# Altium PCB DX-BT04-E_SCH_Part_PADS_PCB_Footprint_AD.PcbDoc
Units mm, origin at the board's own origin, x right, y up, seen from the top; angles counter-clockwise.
Board outline 152.4 x 101.6 mm, 2 copper layers (Top, Bottom), stack 0.323 mm thick; 1 components, 0 nets, 22 pads, 0 vias.
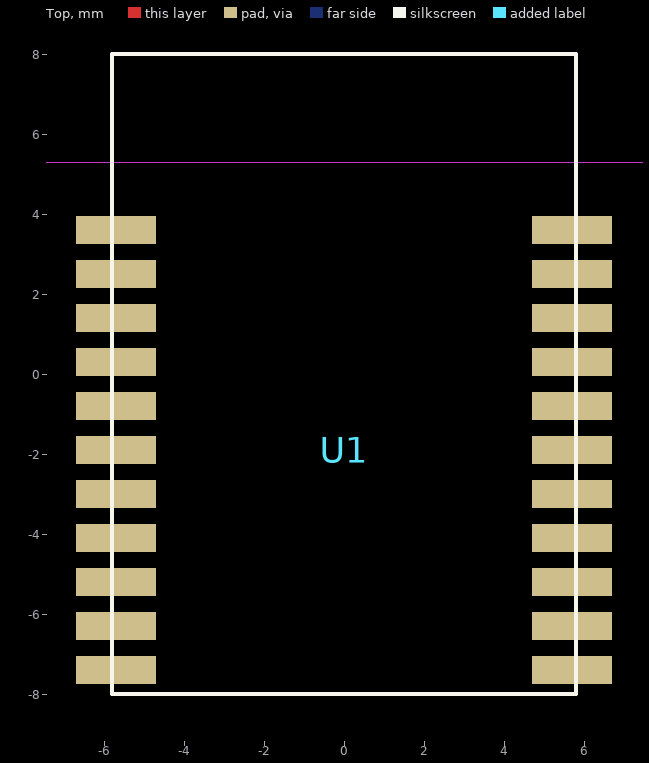
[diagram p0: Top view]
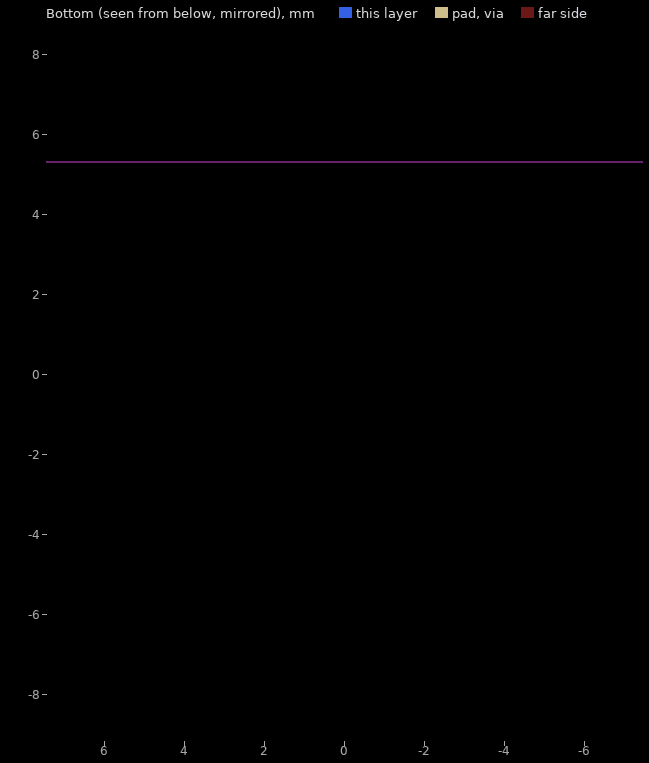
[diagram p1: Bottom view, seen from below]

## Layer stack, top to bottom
Solder Mask Top: solder mask 0.0102, Solder Resist, Dk 3.5
Top: signal copper 0.0343
Dielectric 1: dielectric 0.254, FR-4, Dk 4.3
Bottom: signal copper 0.0343
Solder Mask Bottom: solder mask 0.0102, Solder Resist, Dk 3.5

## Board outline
-694.363,-676.631 -541.963,-676.631 -541.963,-575.031 -694.363,-575.031

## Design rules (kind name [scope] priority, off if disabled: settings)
Clearance "'Default' PADS rule_17" [All] p1: gap=0.152 ignorepadtopadclearanceinfootprint=FALSE except(0: Arc-Hole Track-Hole SMDPad-Hole THPad-Hole Via-Hole Fill-Hole Poly-Hole Region-Hole Text-Hole)
Clearance "'Default' PADS rule_16" [InPolygon vs InPolygon] p2: gap=0.2 ignorepadtopadclearanceinfootprint=FALSE except(0: Arc-Hole Track-Hole SMDPad-Hole THPad-Hole Via-Hole Fill-Hole Poly-Hole Region-Hole Text-Hole)
Clearance "'Default' PADS rule_15" [All] p3: gap=0.152 ignorepadtopadclearanceinfootprint=FALSE except(0: Arc-Hole Track-Hole SMDPad-Hole THPad-Hole Via-Hole Fill-Hole Poly-Hole Region-Hole Text-Hole)
ComponentClearance "'Default' PADS rule_12" [All] p1: gap=0 collisioncheckmode=3 verticalgap=0.254 showdistances=FALSE
FlightTimeFalling "'Default' PADS rule_10" [All] p1: maximum=10.00
FlightTimeRising "'Default' PADS rule_9" [All] p1: maximum=10.00
Length "'Default' PADS rule_5" [All] p1: maxlimit=1270 minlimit=0
MatchedLengths "'Default' PADS rule_11" [InNetClass('All Nets')] p1: tolerance=5.08 checknetsindiffpair=TRUE checkdiffpairvsdiffpair=FALSE checkxsignals=FALSE checkothers=FALSE
MaxMinImpedance "'Default' PADS rule_8" [All] p1: minimum=50.00 maximum=150.0
ParallelSegment "'Default' PADS rule_7" [All] p1: limit=25.4 gap=5.08
ParallelSegment "'Default' PADS rule_6" [All] p2: limit=25.4 gap=5.08
PlaneClearance "'Default' PADS rule_14" [All] p1: clearance=0.2
PlaneConnect "Power Plane Connect Style - Via from round thru-hole global defaults" [IsVia] p1: planeconnectstyle=Direct reliefexpansion=0.508 reliefentries=4 reliefconductorwidth=0.381 reliefairgap=0.254
PlaneConnect "Power Plane Connect Style - Round thru-hole pad from global defaults" [IsPad And OnMultiLayer And (PadShape_MidLayer1 = 'Round') And (PadXSize_MidLayer1 = PadYSize_MidLayer1)] p2: planeconnectstyle=Direct reliefexpansion=0.508 reliefentries=4 reliefconductorwidth=0.381 reliefairgap=0.254
PlaneConnect "Power Plane Connect Style - Square thru-hole pad from global defaults" [IsPad And OnMultiLayer And ((PadShape_MidLayer1 = 'Rectangular') Or (PadShape_MidLayer1 = 'Octagonal') Or (PadShape_MidLayer1 = 'Rounded Rectangle')) And (PadXSize_MidLayer1 = PadYSize_MidLayer1)] p3: planeconnectstyle=Direct reliefexpansion=0.508 reliefentries=4 reliefconductorwidth=0.381 reliefairgap=0.254
PlaneConnect "Power Plane Connect Style - Rect thru-hole pad from global defaults" [IsPad And OnMultiLayer And ((PadShape_MidLayer1 = 'Rectangular') Or (PadShape_MidLayer1 = 'Octagonal') Or (PadShape_MidLayer1 = 'Rounded Rectangle')) And (PadXSize_MidLayer1 <> PadYSize_MidLayer1)] p4: planeconnectstyle=Direct reliefexpansion=0.508 reliefentries=4 reliefconductorwidth=0.381 reliefairgap=0.254
PlaneConnect "Power Plane Connect Style - Square-rect thru-hole pad from global defaults" [IsPad And OnMultiLayer And (PadShape_MidLayer1 = 'Rounded Rectangle') And (PadXSize_MidLayer1 = PadYSize_MidLayer1) And (Pad_CornerRadius_MidLayer1 = '0%')] p5: planeconnectstyle=Direct reliefexpansion=0.508 reliefentries=4 reliefconductorwidth=0.381 reliefairgap=0.254
PlaneConnect "Power Plane Connect Style - Oval thru-hole pad from global defaults" [IsPad And OnMultiLayer And (PadShape_MidLayer1 = 'Round') And (PadXSize_MidLayer1 <> PadYSize_MidLayer1)] p6: planeconnectstyle=Direct reliefexpansion=0.508 reliefentries=4 reliefconductorwidth=0.381 reliefairgap=0.254
PlaneConnect "Power Plane Connect Style - Round-oval thru-hole pad from global defaults" [IsPad And OnMultiLayer And (PadShape_MidLayer1 = 'Rounded Rectangle') And (PadXSize_MidLayer1 = PadYSize_MidLayer1) And (Pad_CornerRadius_MidLayer1 = '100%')] p7: planeconnectstyle=Direct reliefexpansion=0.508 reliefentries=4 reliefconductorwidth=0.381 reliefairgap=0.254
PolygonConnect "Polygon Connect Style - Bottom Round SMD from global defaults" [IsSMTPin And (PadShape_BottomLayer = 'Round') And (PadXSize_BottomLayer = PADYSize_BottomLayer) vs Layer = 'Bottom'] p1: connectstyle=Direct reliefconductorwidth=0.254 reliefentries=4 polygonreliefangle="45 Angle" airgapwidth=0.254
PolygonConnect "Polygon Connect Style - Top Round SMD from global defaults" [IsSMTPin And (PadShape_TopLayer = 'Round') And (PadXSize_TopLayer = PADYSize_TopLayer) vs Layer = 'Top'] p2: connectstyle=Direct reliefconductorwidth=0.254 reliefentries=4 polygonreliefangle="45 Angle" airgapwidth=0.254
PolygonConnect "Polygon Connect Style - Bottom Square SMD from global defaults 1" [IsSMTPin And (PadShape_BottomLayer = 'Rectangular') And (PadXSize_BottomLayer = PADYSize_BottomLayer) vs Layer = 'Bottom'] p3: connectstyle=Direct reliefconductorwidth=0.254 reliefentries=4 polygonreliefangle="45 Angle" airgapwidth=0.254
PolygonConnect "Polygon Connect Style - Bottom Square SMD from global defaults 2" [IsSMTPin And (PadShape_BottomLayer = 'Octagonal') And (PadXSize_BottomLayer = PADYSize_BottomLayer) vs Layer = 'Bottom'] p4: connectstyle=Direct reliefconductorwidth=0.254 reliefentries=4 polygonreliefangle="45 Angle" airgapwidth=0.254
PolygonConnect "Polygon Connect Style - Bottom Square SMD from global defaults 3" [IsSMTPin And (PadShape_BottomLayer = 'Rounded Rectangle') And (PadXSize_BottomLayer = PADYSize_BottomLayer) vs Layer = 'Bottom'] p5: connectstyle=Direct reliefconductorwidth=0.254 reliefentries=4 polygonreliefangle="45 Angle" airgapwidth=0.254
PolygonConnect "Polygon Connect Style - Top Square SMD from global defaults 1" [IsSMTPin And (PadShape_TopLayer = 'Rectangular') And (PadXSize_TopLayer = PADYSize_TopLayer) vs Layer = 'Top'] p6: connectstyle=Direct reliefconductorwidth=0.254 reliefentries=4 polygonreliefangle="45 Angle" airgapwidth=0.254
PolygonConnect "Polygon Connect Style - Top Square SMD from global defaults 2" [IsSMTPin And (PadShape_TopLayer = 'Octagonal') And (PadXSize_TopLayer = PADYSize_TopLayer) vs Layer = 'Top'] p7: connectstyle=Direct reliefconductorwidth=0.254 reliefentries=4 polygonreliefangle="45 Angle" airgapwidth=0.254
PolygonConnect "Polygon Connect Style - Top Square SMD from global defaults 3" [IsSMTPin And (PadShape_TopLayer = 'Rounded Rectangle') And (PadXSize_TopLayer = PADYSize_TopLayer) vs Layer = 'Top'] p8: connectstyle=Direct reliefconductorwidth=0.254 reliefentries=4 polygonreliefangle="45 Angle" airgapwidth=0.254
PolygonConnect "Polygon Connect Style - Bottom Rect SMD from global defaults 1" [IsSMTPin And (PadShape_BottomLayer = 'Rectangular') And (PadXSize_BottomLayer <> PADYSize_BottomLayer) vs Layer = 'Bottom'] p9: connectstyle=Direct reliefconductorwidth=0.254 reliefentries=4 polygonreliefangle="45 Angle" airgapwidth=0.254
PolygonConnect "Polygon Connect Style - Bottom Rect SMD from global defaults 2" [IsSMTPin And (PadShape_BottomLayer = 'Octagonal') And (PadXSize_BottomLayer <> PADYSize_BottomLayer) vs Layer = 'Bottom'] p10: connectstyle=Direct reliefconductorwidth=0.254 reliefentries=4 polygonreliefangle="45 Angle" airgapwidth=0.254
PolygonConnect "Polygon Connect Style - Bottom Rect SMD from global defaults 3" [IsSMTPin And (PadShape_BottomLayer = 'Rounded Rectangle') And (PadXSize_BottomLayer <> PADYSize_BottomLayer) vs Layer = 'Bottom'] p11: connectstyle=Direct reliefconductorwidth=0.254 reliefentries=4 polygonreliefangle="45 Angle" airgapwidth=0.254
PolygonConnect "Polygon Connect Style - Bottom Square-rect SMD pad from global defaults" [IsSMTPin And (PadShape_BottomLayer = 'Rounded Rectangle') And (PadXSize_BottomLayer = PADYSize_BottomLayer) And (Pad_CornerRadius_BottomLayer = '0%') vs Layer = 'Bottom'] p12: connectstyle=Direct reliefconductorwidth=0.254 reliefentries=4 polygonreliefangle="45 Angle" airgapwidth=0.254
PolygonConnect "Polygon Connect Style - Top Rect SMD from global defaults 1" [IsSMTPin And (PadShape_TopLayer = 'Rectangular') And (PadXSize_TopLayer <> PADYSize_TopLayer) vs Layer = 'Top'] p13: connectstyle=Direct reliefconductorwidth=0.254 reliefentries=4 polygonreliefangle="45 Angle" airgapwidth=0.254
PolygonConnect "Polygon Connect Style - Top Rect SMD from global defaults 2" [IsSMTPin And (PadShape_TopLayer = 'Octagonal') And (PadXSize_TopLayer <> PADYSize_TopLayer) vs Layer = 'Top'] p14: connectstyle=Direct reliefconductorwidth=0.254 reliefentries=4 polygonreliefangle="45 Angle" airgapwidth=0.254
PolygonConnect "Polygon Connect Style - Top Rect SMD from global defaults 3" [IsSMTPin And (PadShape_TopLayer = 'Rounded Rectangle') And (PadXSize_TopLayer <> PADYSize_TopLayer) vs Layer = 'Top'] p15: connectstyle=Direct reliefconductorwidth=0.254 reliefentries=4 polygonreliefangle="45 Angle" airgapwidth=0.254
PolygonConnect "Polygon Connect Style - Top Square-rect SMD pad from global defaults" [IsSMTPin And (PadShape_TopLayer = 'Rounded Rectangle') And (PadXSize_TopLayer = PADYSize_TopLayer) And (Pad_CornerRadius_TopLayer = '0%') vs Layer = 'Top'] p16: connectstyle=Direct reliefconductorwidth=0.254 reliefentries=4 polygonreliefangle="45 Angle" airgapwidth=0.254
PolygonConnect "Polygon Connect Style - Bottom Oval SMD from global defaults" [IsSMTPin And (PadShape_BottomLayer = 'Round') And (PadXSize_BottomLayer <> PADYSize_BottomLayer) vs Layer = 'Bottom'] p17: connectstyle=Direct reliefconductorwidth=0.254 reliefentries=4 polygonreliefangle="45 Angle" airgapwidth=0.254
PolygonConnect "Polygon Connect Style - Bottom Round-oval SMD pad from global defaults" [IsSMTPin And (PadShape_BottomLayer = 'Rounded Rectangle') And (PadXSize_BottomLayer = PADYSize_BottomLayer) And (Pad_CornerRadius_BottomLayer = '100%') vs Layer = 'Bottom'] p18: connectstyle=Direct reliefconductorwidth=0.254 reliefentries=4 polygonreliefangle="45 Angle" airgapwidth=0.254
PolygonConnect "Polygon Connect Style - Top Oval SMD from global defaults" [IsSMTPin And (PadShape_TopLayer = 'Round') And (PadXSize_TopLayer <> PADYSize_TopLayer) vs Layer = 'Top'] p19: connectstyle=Direct reliefconductorwidth=0.254 reliefentries=4 polygonreliefangle="45 Angle" airgapwidth=0.254
PolygonConnect "Polygon Connect Style - Top Round-oval SMD pad from global defaults" [IsSMTPin And (PadShape_TopLayer = 'Rounded Rectangle') And (PadXSize_TopLayer = PADYSize_TopLayer) And (Pad_CornerRadius_TopLayer = '100%') vs Layer = 'Top'] p20: connectstyle=Direct reliefconductorwidth=0.254 reliefentries=4 polygonreliefangle="45 Angle" airgapwidth=0.254
PolygonConnect "Polygon Connect Style - Via from round thru-hole global defaults_18" [IsVia] p21: connectstyle=Direct reliefconductorwidth=0.381 reliefentries=4 polygonreliefangle="45 Angle" airgapwidth=0.254
PolygonConnect "Polygon Connect Style - Bottom Round thru-hole pad from global defaults" [IsPad And OnMultiLayer And (PadShape_BottomLayer = 'Round') And (PadXSize_BottomLayer = PADYSize_BottomLayer) vs Layer = 'Bottom'] p22: connectstyle=Direct reliefconductorwidth=0.381 reliefentries=4 polygonreliefangle="45 Angle" airgapwidth=0.254
PolygonConnect "Polygon Connect Style - Via from round thru-hole global defaults" [IsVia] p23: connectstyle=Direct reliefconductorwidth=0.381 reliefentries=4 polygonreliefangle="45 Angle" airgapwidth=0.254
PolygonConnect "Polygon Connect Style - Top Round thru-hole pad from global defaults" [IsPad And OnMultiLayer And (PadShape_TopLayer = 'Round') And (PadXSize_TopLayer = PADYSize_TopLayer) vs Layer = 'Top'] p24: connectstyle=Direct reliefconductorwidth=0.381 reliefentries=4 polygonreliefangle="45 Angle" airgapwidth=0.254
PolygonConnect "Polygon Connect Style - Bottom Square thru-hole pad from global defaults" [IsPad And OnMultiLayer And ((PadShape_BottomLayer = 'Rectangular') Or (PadShape_BottomLayer = 'Octagonal') Or (PadShape_BottomLayer = 'Rounded Rectangle')) And (PadXSize_BottomLayer = PADYSize_BottomLayer) vs Layer = 'Bottom'] p25: connectstyle=Direct reliefconductorwidth=0.381 reliefentries=4 polygonreliefangle="45 Angle" airgapwidth=0.254
PolygonConnect "Polygon Connect Style - Top Square thru-hole pad from global defaults" [IsPad And OnMultiLayer And ((PadShape_TopLayer = 'Rectangular') Or (PadShape_TopLayer = 'Octagonal') Or (PadShape_TopLayer = 'Rounded Rectangle')) And (PadXSize_TopLayer = PADYSize_TopLayer) vs Layer = 'Top'] p26: connectstyle=Direct reliefconductorwidth=0.381 reliefentries=4 polygonreliefangle="45 Angle" airgapwidth=0.254
PolygonConnect "Polygon Connect Style - Bottom Rect thru-hole pad from global defaults" [IsPad And OnMultiLayer And ((PadShape_BottomLayer = 'Rectangular') Or (PadShape_BottomLayer = 'Octagonal') Or (PadShape_BottomLayer = 'Rounded Rectangle')) And (PadXSize_BottomLayer <> PADYSize_BottomLayer) vs Layer = 'Bottom'] p27: connectstyle=Direct reliefconductorwidth=0.381 reliefentries=4 polygonreliefangle="45 Angle" airgapwidth=0.254
PolygonConnect "Polygon Connect Style - Bottom Square-rect thru-hole pad from global defaults" [IsPad And OnMultiLayer And (PadShape_BottomLayer = 'Rounded Rectangle') And (PadXSize_BottomLayer = PADYSize_BottomLayer) And (Pad_CornerRadius_BottomLayer = '0%') vs Layer = 'Bottom'] p28: connectstyle=Direct reliefconductorwidth=0.381 reliefentries=4 polygonreliefangle="45 Angle" airgapwidth=0.254
PolygonConnect "Polygon Connect Style - Top Rect thru-hole pad from global defaults" [IsPad And OnMultiLayer And ((PadShape_TopLayer = 'Rectangular') Or (PadShape_TopLayer = 'Octagonal') Or (PadShape_TopLayer = 'Rounded Rectangle')) And (PadXSize_TopLayer <> PADYSize_TopLayer) vs Layer = 'Top'] p29: connectstyle=Direct reliefconductorwidth=0.381 reliefentries=4 polygonreliefangle="45 Angle" airgapwidth=0.254
PolygonConnect "Polygon Connect Style - Top Square-rect thru-hole pad from global defaults" [IsPad And OnMultiLayer And (PadShape_TopLayer = 'Rounded Rectangle') And (PadXSize_TopLayer = PADYSize_TopLayer) And (Pad_CornerRadius_TopLayer = '0%') vs Layer = 'Top'] p30: connectstyle=Direct reliefconductorwidth=0.381 reliefentries=4 polygonreliefangle="45 Angle" airgapwidth=0.254
PolygonConnect "Polygon Connect Style - Bottom Oval thru-hole pad from global defaults" [IsPad And OnMultiLayer And (PadShape_BottomLayer = 'Round') And (PadXSize_BottomLayer <> PADYSize_BottomLayer) vs Layer = 'Bottom'] p31: connectstyle=Direct reliefconductorwidth=0.381 reliefentries=4 polygonreliefangle="45 Angle" airgapwidth=0.254
PolygonConnect "Polygon Connect Style - Bottom Round-oval thru-hole pad from global defaults" [IsPad And OnMultiLayer And (PadShape_BottomLayer = 'Rounded Rectangle') And (PadXSize_BottomLayer = PADYSize_BottomLayer) And (Pad_CornerRadius_BottomLayer = '100%') vs Layer = 'Bottom'] p32: connectstyle=Direct reliefconductorwidth=0.381 reliefentries=4 polygonreliefangle="45 Angle" airgapwidth=0.254
PolygonConnect "Polygon Connect Style - Top Oval thru-hole pad from global defaults" [IsPad And OnMultiLayer And (PadShape_TopLayer = 'Round') And (PadXSize_TopLayer <> PADYSize_TopLayer) vs Layer = 'Top'] p33: connectstyle=Direct reliefconductorwidth=0.381 reliefentries=4 polygonreliefangle="45 Angle" airgapwidth=0.254
PolygonConnect "Polygon Connect Style - Top Round-oval thru-hole pad from global defaults" [IsPad And OnMultiLayer And (PadShape_TopLayer = 'Rounded Rectangle') And (PadXSize_TopLayer = PADYSize_TopLayer) And (Pad_CornerRadius_TopLayer = '100%') vs Layer = 'Top'] p34: connectstyle=Direct reliefconductorwidth=0.381 reliefentries=4 polygonreliefangle="45 Angle" airgapwidth=0.254
PolygonConnect [All] p35: connectstyle=Relief reliefconductorwidth=0.254 reliefentries=4 polygonreliefangle="90 Angle" airgapwidth=0.254
RoutingLayers "'Default' PADS rule_3" [All] p1: top layer_v5=TRUE bottom layer_v5=TRUE
RoutingPriority "'Default' PADS rule_2" [All] p1: routingpriority=3
RoutingTopology "'Default' PADS rule" [All] p1: topology=Shortest
RoutingVias "'Default' PADS rule_4" [All] p1: holewidth=0.23 width=0.5 viastyle="Through Hole" minholewidth=0.23 minwidth=0.5 maxholewidth=0.23 maxwidth=0.5
SolderMaskExpansion [All] p1: expansion=0.102
Width "'Default' PADS rule_13" [All] p1: maxlimit=0.152 minlimit=0.152 preferedwidth=0.152
24 further rules are at their usual default settings.

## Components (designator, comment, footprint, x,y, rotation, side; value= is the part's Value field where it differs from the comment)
U1 "Comment" DX-BT04-E 0,0 r0 top

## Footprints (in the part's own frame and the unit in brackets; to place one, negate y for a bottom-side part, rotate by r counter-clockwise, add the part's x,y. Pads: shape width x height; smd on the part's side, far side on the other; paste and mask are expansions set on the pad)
DX-BT04-E [mm] "DX-BT04-E"
  rect 2x0.7 smd: 1(-5.7,3.6) 2(-5.7,2.5) 3(-5.7,1.4) 4(-5.7,0.3) 5(-5.7,-0.8) 6(-5.7,-1.9) 7(-5.7,-3) 8(-5.7,-4.1) 9(-5.7,-5.2) 10(-5.7,-6.3) 11(-5.7,-7.4) 12(5.7,-7.4) 13(5.7,-6.3) 14(5.7,-5.2) 15(5.7,-4.1) 16(5.7,-3) 17(5.7,-1.9) 18(5.7,-0.8) 19(5.7,0.3) 20(5.7,1.4) 21(5.7,2.5) 22(5.7,3.6)
  silkscreen extent -5.8,-8 5.8,8

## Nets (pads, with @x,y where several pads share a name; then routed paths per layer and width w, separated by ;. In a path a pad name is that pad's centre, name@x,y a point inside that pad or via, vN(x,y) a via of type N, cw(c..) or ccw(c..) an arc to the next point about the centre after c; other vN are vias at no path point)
pads on no net: U1.1 U1.2 U1.3 U1.4 U1.5 U1.6 U1.7 U1.8 U1.9 U1.10 U1.11 U1.12 U1.13 U1.14 U1.15 U1.16 U1.17 U1.18 U1.19 U1.20 U1.21 U1.22

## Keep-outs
Keep-Out Layer:
  region: -10.7,12.9 -10.7,5.3 10.7,5.3 10.7,12.9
